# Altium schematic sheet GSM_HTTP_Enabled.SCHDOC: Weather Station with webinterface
size C; Organization: Altium Limited; Address1: L3, 12a Rodborough Rd; Address2: Frenchs Forest; Address3: NSW; Address4: Australia 2086; DocumentNumber: 1; SheetNumber: 1; SheetTotal: 2
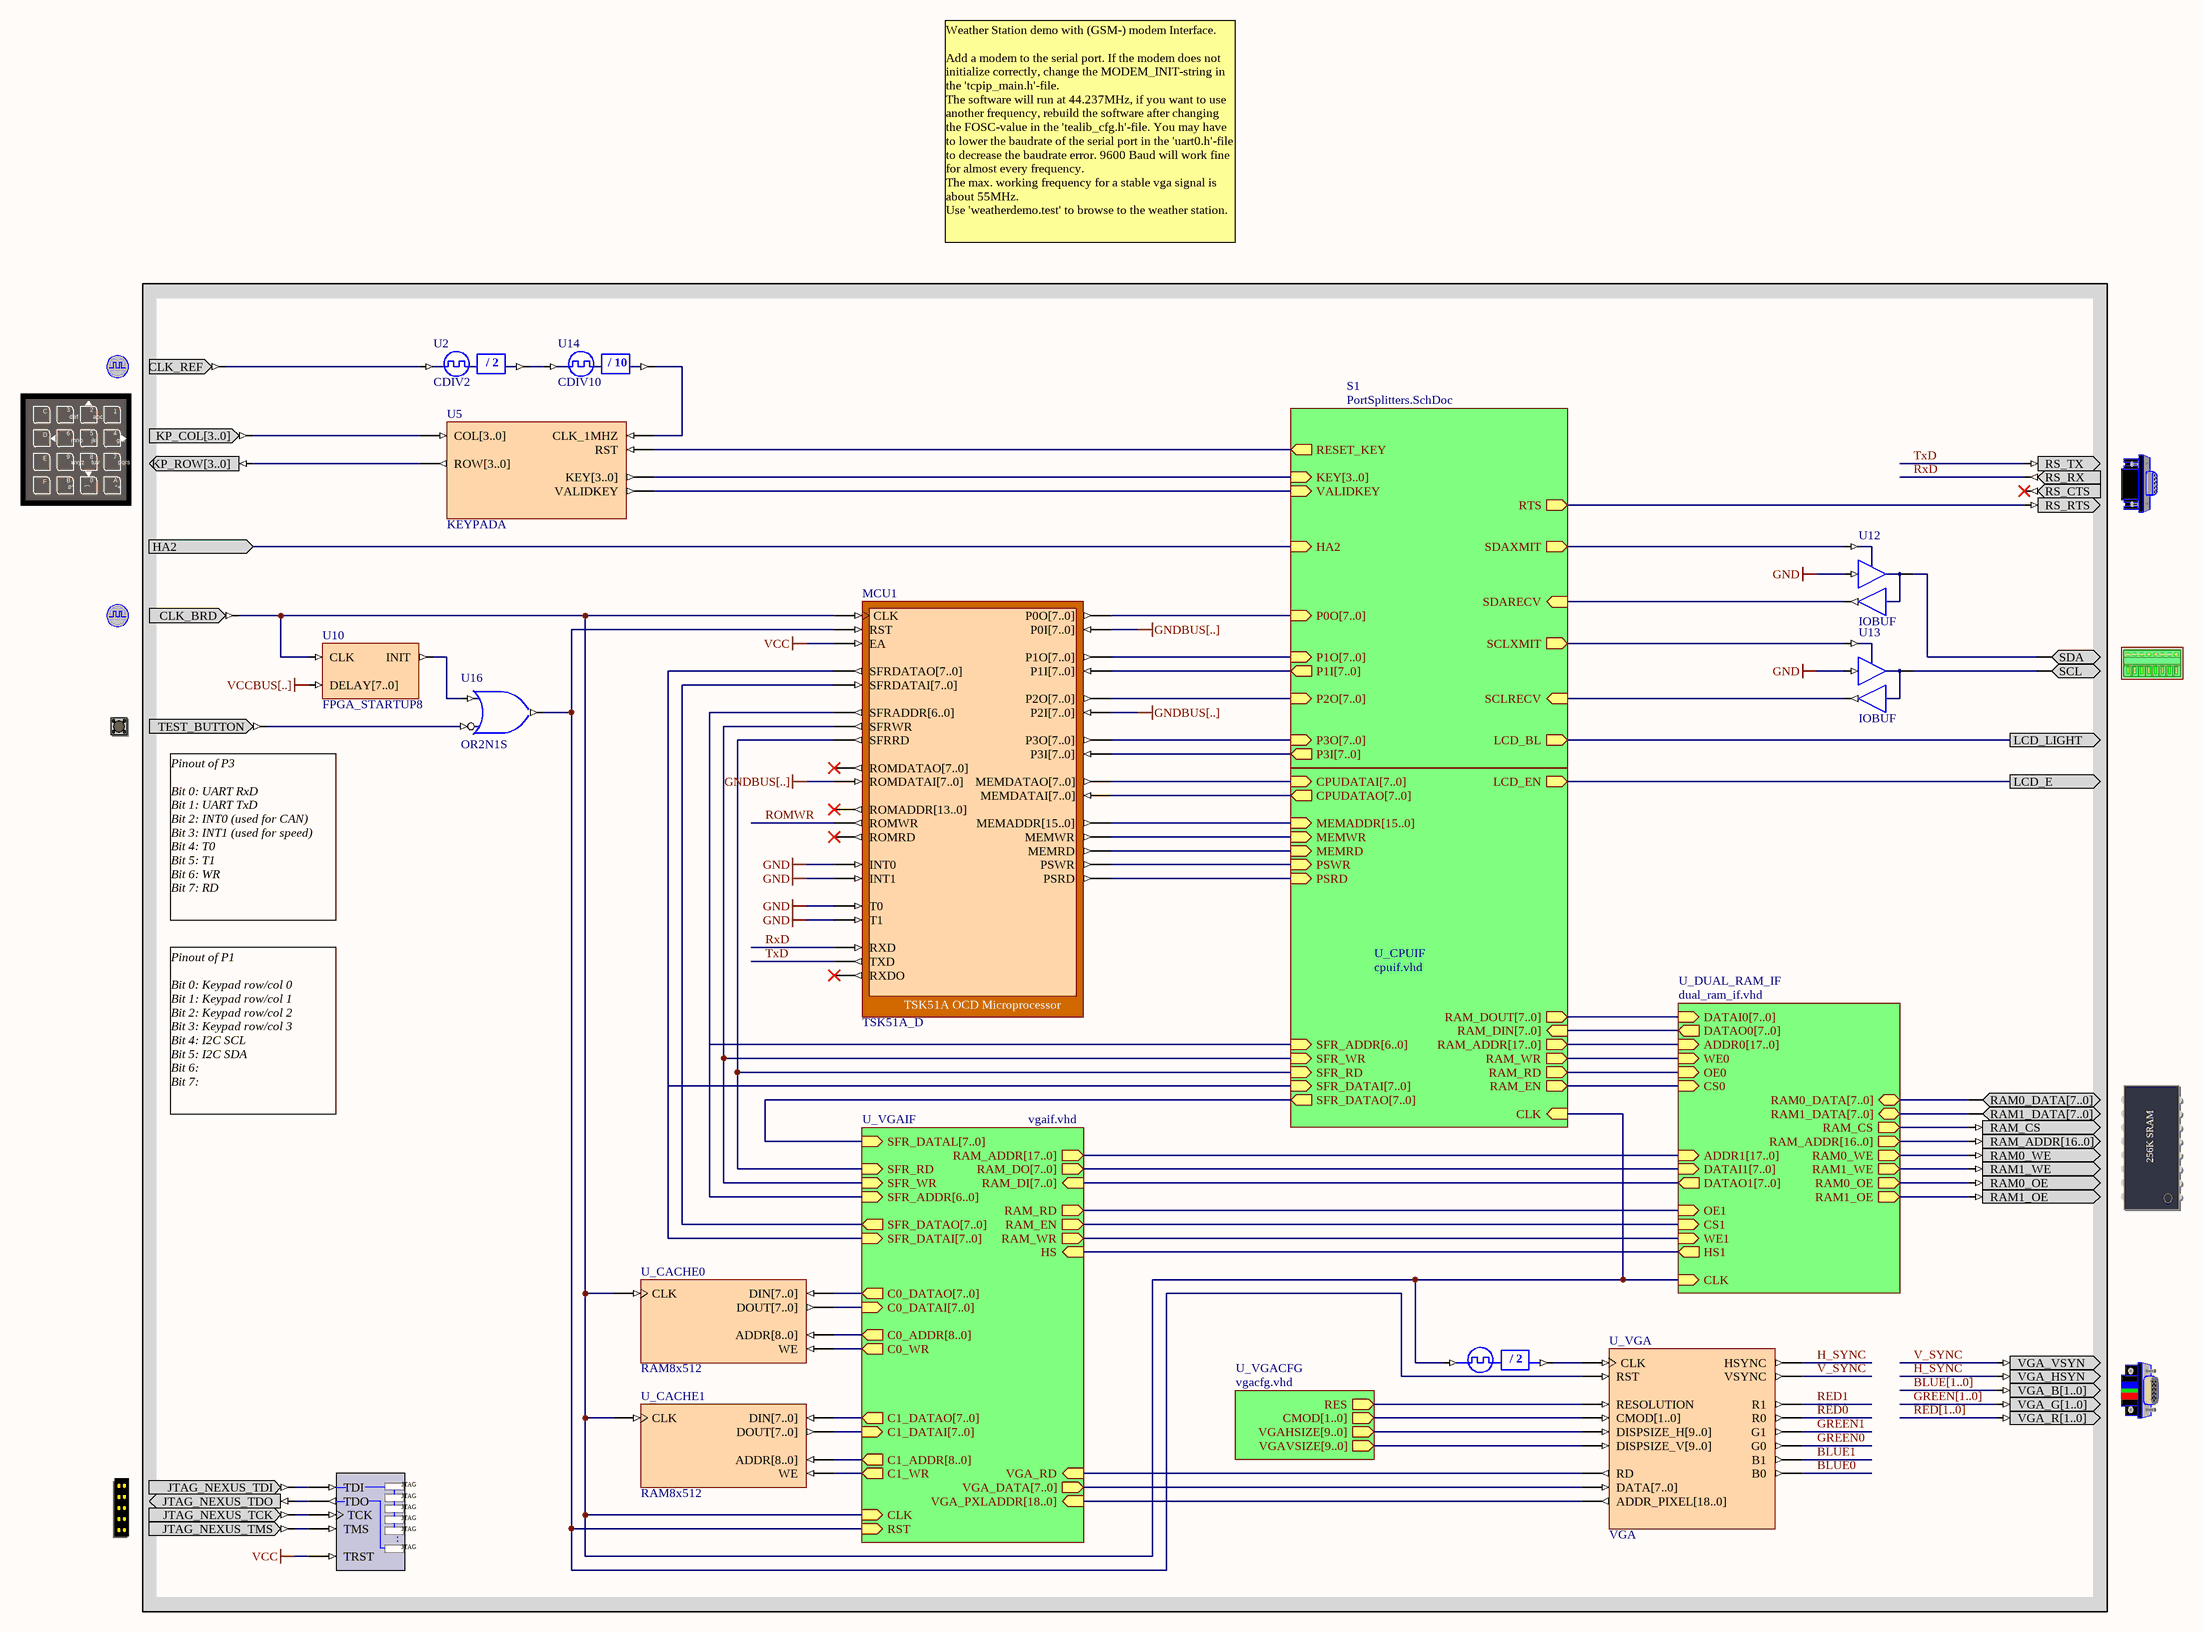
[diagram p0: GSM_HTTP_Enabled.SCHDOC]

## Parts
(Parts that share a designator on the sheet are numbered #1, #2 ... from top to bottom, then left to right.)
?#1  CLOCK_REFERENCE  (value not drawn)
?#2  KEYPAD  (value not drawn)
?#3  RS232CNTR  (value not drawn)
?#4  CLOCK_BOARD  (value not drawn)
?#5  ADCDAC_I2C  (value not drawn)
?#6  TEST_BUTTON  (value not drawn)
?#7  MEMORY256KX8  (value not drawn)
?#8  VGACNTR  (value not drawn)
?#9  NEXUS_JTAG_CONNECTOR  (value not drawn)
MCU1  TSK51A_D
NEXUS_JTAG_PORT  NEXUS_JTAG_PORT  (value not drawn)
U2  CDIV2
U5  KEYPADA
U10  FPGA_STARTUP8
U12  IOBUF
U13  IOBUF
U14  CDIV10
U16  OR2N1S
U_CACHE0  RAM8x512
U_CACHE1  RAM8x512
U_DIV2  CDIV2  (value not drawn)
U_VGA  VGA

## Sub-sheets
S1 = PortSplitters.SchDoc: P0O[7..0] (in), P1O[7..0] (in), P1I[7..0] (out), P2O[7..0] (in), P3O[7..0] (in), P3I[7..0] (out), HA2 (in), SCLXMIT (out), LCD_BL (out), RTS (out), SDAXMIT (out), VALIDKEY (in), KEY[3..0] (in), SCLRECV (in), SDARECV (in), RESET_KEY (out)
U_CPUIF = cpuif.vhd: MEMWR (in), RAM_EN (out), RAM_WR (out), RAM_RD (out), RAM_DOUT[7..0] (out), MEMRD (in), LCD_EN (out), RAM_ADDR[17..0] (out), CLK (in), SFR_ADDR[6..0] (in), SFR_DATAI[7..0] (in), SFR_DATAO[7..0] (out), SFR_WR (in), SFR_RD (in), RAM_DIN[7..0] (in), PSWR (in), PSRD (in), MEMADDR[15..0] (in), CPUDATAI[7..0] (in), CPUDATAO[7..0] (out)
U_DUAL_RAM_IF = dual_ram_if.vhd: DATAI0[7..0] (in), DATAI1[7..0] (in), DATAO0[7..0] (out), DATAO1[7..0] (out), ADDR0[17..0] (in), ADDR1[17..0] (in), WE0 (in), WE1 (in), OE0 (in), OE1 (in), CS0 (in), CS1 (in), HS1 (out), RAM0_DATA[7..0] (bidir), RAM1_DATA[7..0] (bidir), RAM_ADDR[16..0] (out), RAM0_WE (out), RAM1_WE (out), RAM0_OE (out), RAM1_OE (out), RAM_CS (out), CLK (in)
U_VGACFG = vgacfg.vhd: RES (out), CMOD[1..0] (out), VGAHSIZE[9..0] (out), VGAVSIZE[9..0] (out)
U_VGAIF = vgaif.vhd: VGA_PXLADDR[18..0] (in), VGA_DATA[7..0] (out), VGA_RD (in), C1_WR (out), C1_ADDR[8..0] (out), C1_DATAI[7..0] (in), C1_DATAO[7..0] (out), C0_WR (out), C0_ADDR[8..0] (out), C0_DATAI[7..0] (in), C0_DATAO[7..0] (out), RAM_ADDR[17..0] (out), CLK (in), HS (in), RAM_DO[7..0] (out), RAM_RD (out), RAM_EN (out), RAM_WR (out), SFR_ADDR[6..0] (in), SFR_DATAI[7..0] (in), SFR_DATAO[7..0] (out), SFR_WR (in), SFR_RD (in), SFR_DATAL[7..0] (in), RAM_DI[7..0] (in), RST (in)

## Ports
HA2 (in), LCD_E (out), LCD_LIGHT (out)

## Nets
GND: MCU1.INT0 MCU1.INT1 MCU1.T0 MCU1.T1 U12.I U13.I
VCC: MCU1.EA NEXUS_JTAG_PORT.TRST
VCCBUS[..]: U10.DELAY[7..0]
BLUE0: U_VGA.B0
BLUE1: U_VGA.B1
GREEN0: U_VGA.G0
GREEN1: U_VGA.G1
H_SYNC: ?#8.VGA_HSYN U_VGA.HSYNC
HA2: port HA2, sheet S1/HA2
LCD_E: port LCD_E, sheet U_CPUIF/LCD_EN
LCD_LIGHT: port LCD_LIGHT, sheet S1/LCD_BL
RED0: U_VGA.R0
RED1: U_VGA.R1
ROMWR: MCU1.ROMWR
RxD: ?#3.RS_RX MCU1.RXD
TxD: ?#3.RS_TX MCU1.TXD
V_SYNC: ?#8.VGA_VSYN U_VGA.VSYNC
Net?#1_CLK_REF: ?#1.CLK_REF U2.CLKIN
Net?#3_RS_RTS: ?#3.RS_RTS ; sheet S1/RTS
Net?#4_CLK_BRD: ?#4.CLK_BRD MCU1.CLK U10.CLK U_CACHE0.CLK U_CACHE1.CLK U_DIV2.CLKIN ; sheet U_CPUIF/CLK, sheet U_VGAIF/CLK, sheet U_DUAL_RAM_IF/CLK
Net?#5_SCL: ?#5.SCL U13.IO
Net?#5_SDA: ?#5.SDA U12.IO
Net?#6_TEST_BUTTON: ?#6.TEST_BUTTON U16.I0
Net?#7_RAM0_OE: ?#7.RAM0_OE ; sheet U_DUAL_RAM_IF/RAM0_OE
Net?#7_RAM0_WE: ?#7.RAM0_WE ; sheet U_DUAL_RAM_IF/RAM0_WE
Net?#7_RAM1_OE: ?#7.RAM1_OE ; sheet U_DUAL_RAM_IF/RAM1_OE
Net?#7_RAM1_WE: ?#7.RAM1_WE ; sheet U_DUAL_RAM_IF/RAM1_WE
Net?#7_RAM_CS: ?#7.RAM_CS ; sheet U_DUAL_RAM_IF/RAM_CS
Net?#9_JTAG_NEXUS_TCK: ?#9.JTAG_NEXUS_TCK NEXUS_JTAG_PORT.TCK
Net?#9_JTAG_NEXUS_TDI: ?#9.JTAG_NEXUS_TDI NEXUS_JTAG_PORT.TDI
Net?#9_JTAG_NEXUS_TDO: ?#9.JTAG_NEXUS_TDO NEXUS_JTAG_PORT.TDO
Net?#9_JTAG_NEXUS_TMS: ?#9.JTAG_NEXUS_TMS NEXUS_JTAG_PORT.TMS
NetMCU1_MEMRD: MCU1.MEMRD ; sheet U_CPUIF/MEMRD
NetMCU1_MEMWR: MCU1.MEMWR ; sheet U_CPUIF/MEMWR
NetMCU1_PSRD: MCU1.PSRD ; sheet U_CPUIF/PSRD
NetMCU1_PSWR: MCU1.PSWR ; sheet U_CPUIF/PSWR
NetMCU1_RST: MCU1.RST U16.O U_VGA.RST ; sheet U_VGAIF/RST
NetMCU1_SFRRD: MCU1.SFRRD ; sheet U_CPUIF/SFR_RD, sheet U_VGAIF/SFR_RD
NetMCU1_SFRWR: MCU1.SFRWR ; sheet U_CPUIF/SFR_WR, sheet U_VGAIF/SFR_WR
NetU2_CLKDV: U2.CLKDV U14.CLKIN
NetU5_CLK_1MHZ: U5.CLK_1MHZ U14.CLKDV
NetU5_RST: U5.RST ; sheet S1/RESET_KEY
NetU5_VALIDKEY: U5.VALIDKEY ; sheet S1/VALIDKEY
NetU10_INIT: U10.INIT U16.I1
NetU12_O: U12.O ; sheet S1/SDARECV
NetU12_T: U12.T ; sheet S1/SDAXMIT
NetU13_O: U13.O ; sheet S1/SCLRECV
NetU13_T: U13.T ; sheet S1/SCLXMIT
NetU_CACHE0_WE: U_CACHE0.WE ; sheet U_VGAIF/C0_WR
NetU_CACHE1_WE: U_CACHE1.WE ; sheet U_VGAIF/C1_WR
NetU_DIV2_CLKDV: U_DIV2.CLKDV U_VGA.CLK
NetU_VGA_RD: U_VGA.RD ; sheet U_VGAIF/VGA_RD
NetU_VGA_RESOLUTION: U_VGA.RESOLUTION ; sheet U_VGACFG/RES
(unnamed): sheet U_CPUIF/RAM_EN, sheet U_DUAL_RAM_IF/CS0
(unnamed): sheet U_CPUIF/RAM_WR, sheet U_DUAL_RAM_IF/WE0  [a separate net that carries the same name]
(unnamed): sheet U_CPUIF/RAM_RD, sheet U_DUAL_RAM_IF/OE0  [a separate net that carries the same name]
(unnamed): sheet U_VGAIF/HS, sheet U_DUAL_RAM_IF/HS1  [a separate net that carries the same name]
(unnamed): sheet U_VGAIF/RAM_RD, sheet U_DUAL_RAM_IF/OE1  [a separate net that carries the same name]
(unnamed): sheet U_VGAIF/RAM_EN, sheet U_DUAL_RAM_IF/CS1  [a separate net that carries the same name]
(unnamed): sheet U_VGAIF/RAM_WR, sheet U_DUAL_RAM_IF/WE1  [a separate net that carries the same name]

Not connected (* = marked no-connect by the designer): ?#2 KP_COL[3..0] KP_ROW[3..0]; ?#3 RS_CTS*; ?#7 RAM0_DATA[7..0] RAM1_DATA[7..0] RAM_ADDR[16..0]; ?#8 VGA_B[1..0] VGA_G[1..0] VGA_R[1..0]; MCU1 MEMADDR[15..0] MEMDATAI[7..0] MEMDATAO[7..0] P0I[7..0] P0O[7..0] P1I[7..0] P1O[7..0] P2I[7..0] P2O[7..0] P3I[7..0] P3O[7..0] ROMADDR[13..0]* ROMDATAI[7..0] ROMDATAO[7..0]* ROMRD* RXDO* SFRADDR[6..0] SFRDATAI[7..0] SFRDATAO[7..0]; U5 COL[3..0] KEY[3..0] ROW[3..0]; U_CACHE0 ADDR[8..0] DIN[7..0] DOUT[7..0]; U_CACHE1 ADDR[8..0] DIN[7..0] DOUT[7..0]; U_VGA ADDR_PIXEL[18..0] CMOD[1..0] DATA[7..0] DISPSIZE_H[9..0] DISPSIZE_V[9..0]

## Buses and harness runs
bus BLUE[1..0]
bus GREEN[1..0]
bus RED[1..0]
bus sheet U_CPUIF/RAM_ADDR[17..0] = sheet U_DUAL_RAM_IF/ADDR0[17..0]
bus sheet U_CPUIF/RAM_DIN[7..0] = sheet U_DUAL_RAM_IF/DATAO0[7..0]
bus sheet U_CPUIF/RAM_DOUT[7..0] = sheet U_DUAL_RAM_IF/DATAI0[7..0]
bus sheet U_CPUIF/SFR_ADDR[6..0] = sheet U_VGAIF/SFR_ADDR[6..0]
bus sheet U_CPUIF/SFR_DATAI[7..0] = sheet U_VGAIF/SFR_DATAI[7..0]
bus sheet U_CPUIF/SFR_DATAO[7..0] = sheet U_VGAIF/SFR_DATAL[7..0]
bus sheet U_DUAL_RAM_IF/ADDR1[17..0] = sheet U_VGAIF/RAM_ADDR[17..0]
bus sheet U_DUAL_RAM_IF/DATAI1[7..0] = sheet U_VGAIF/RAM_DO[7..0]
bus sheet U_DUAL_RAM_IF/DATAO1[7..0] = sheet U_VGAIF/RAM_DI[7..0]

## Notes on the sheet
- Weather Station demo with (GSM-) modem Interface.
  Add a modem to the serial port. If the modem does not initialize correctly, change the MODEM_INIT-string in the 'tcpip_main.h'-file.
  The software will run at 44.237MHz, if you want to use another frequency, rebuild the software after changing the FOSC-value in the 'tealib_cfg.h'-file. You may have to lower the baudrate of the serial port in the 'uart0.h'-file to decrease the baudrate error. 9600 Baud will work fine for almost every frequency.
  The max. working frequency for a stable vga signal is about 55MHz.
  Use 'weatherdemo.test' to browse to the weather station.
- Pinout of P3
  Bit 0: UART RxD
  Bit 1: UART TxD
  Bit 2: INT0 (used for CAN)
  Bit 3: INT1 (used for speed)
  Bit 4: T0
  Bit 5: T1
  Bit 6: WR
  Bit 7: RD
- Pinout of P1
  Bit 0: Keypad row/col 0
  Bit 1: Keypad row/col 1
  Bit 2: Keypad row/col 2
  Bit 3: Keypad row/col 3
  Bit 4: I2C SCL
  Bit 5: I2C SDA
  Bit 6:
  Bit 7:
- Labels drawn without touching a wire or pin: GNDBUS[..]

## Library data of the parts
?#1 = CLOCK_REFERENCE: Global System Clock Reference Supply; PortComponent: True
?#2 = KEYPAD: Key Pad; PortComponent: True
?#3 = RS232CNTR: DCE Serial Port Connector; PortComponent: True
?#4 = CLOCK_BOARD: Global System Clock Supply; PortComponent: True
?#5 = ADCDAC_I2C: Analog Digital/ Digital Analog Converter, I2C Interface; PortComponent: True
?#6 = TEST_BUTTON: Test Button; PortComponent: True
?#7 = MEMORY256KX8: SRAM 256kx8; PortComponent: True
?#8 = VGACNTR: VGA Dsub-15-Female-HD; PortComponent: True
?#9 = NEXUS_JTAG_CONNECTOR: JTAG Port; PortComponent: True
MCU1 = TSK51A_D: TSK51A OCD Microprocessor; NEXUS_CORE: Processor_OCDS; NEXUS_JTAG_DEVICE: True; NEXUS_JTAG_ORDER: 0; ChildModel1: RAM256x8_TSK51D
NEXUS_JTAG_PORT = NEXUS_JTAG_PORT: Nexus Processor JTAG Chain Connector; NEXUS_JTAG_CONNECTOR: True
U2 U_DIV2 = CDIV2: Clock Divider by 2; ArchiveName: GENERIC
U5 = KEYPADA: Keypad
U10 = FPGA_STARTUP8: FPGA Startup With 8 Bit Delay
U12 U13 = IOBUF: Input/Output Buffer; ArchiveName: GENERIC
U14 = CDIV10: Clock Divider by 10; ArchiveName: GENERIC
U16 = OR2N1S: 2-Input OR Gate with Active Low A Input, Single Pin Version; Xilinx Equivalent: OR2B1; ArchiveName: GENERIC
U_CACHE0 U_CACHE1 = RAM8x512: Single Port Random Access Memory 512 x 8; Memory_Depth: 512; Memory_Type: RAM_SinglePortBlock; Memory_Width: 8; Memory_ClockEdge: Rising; Nexus_Core: Memory_Program
U_VGA = VGA: VGA Controller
